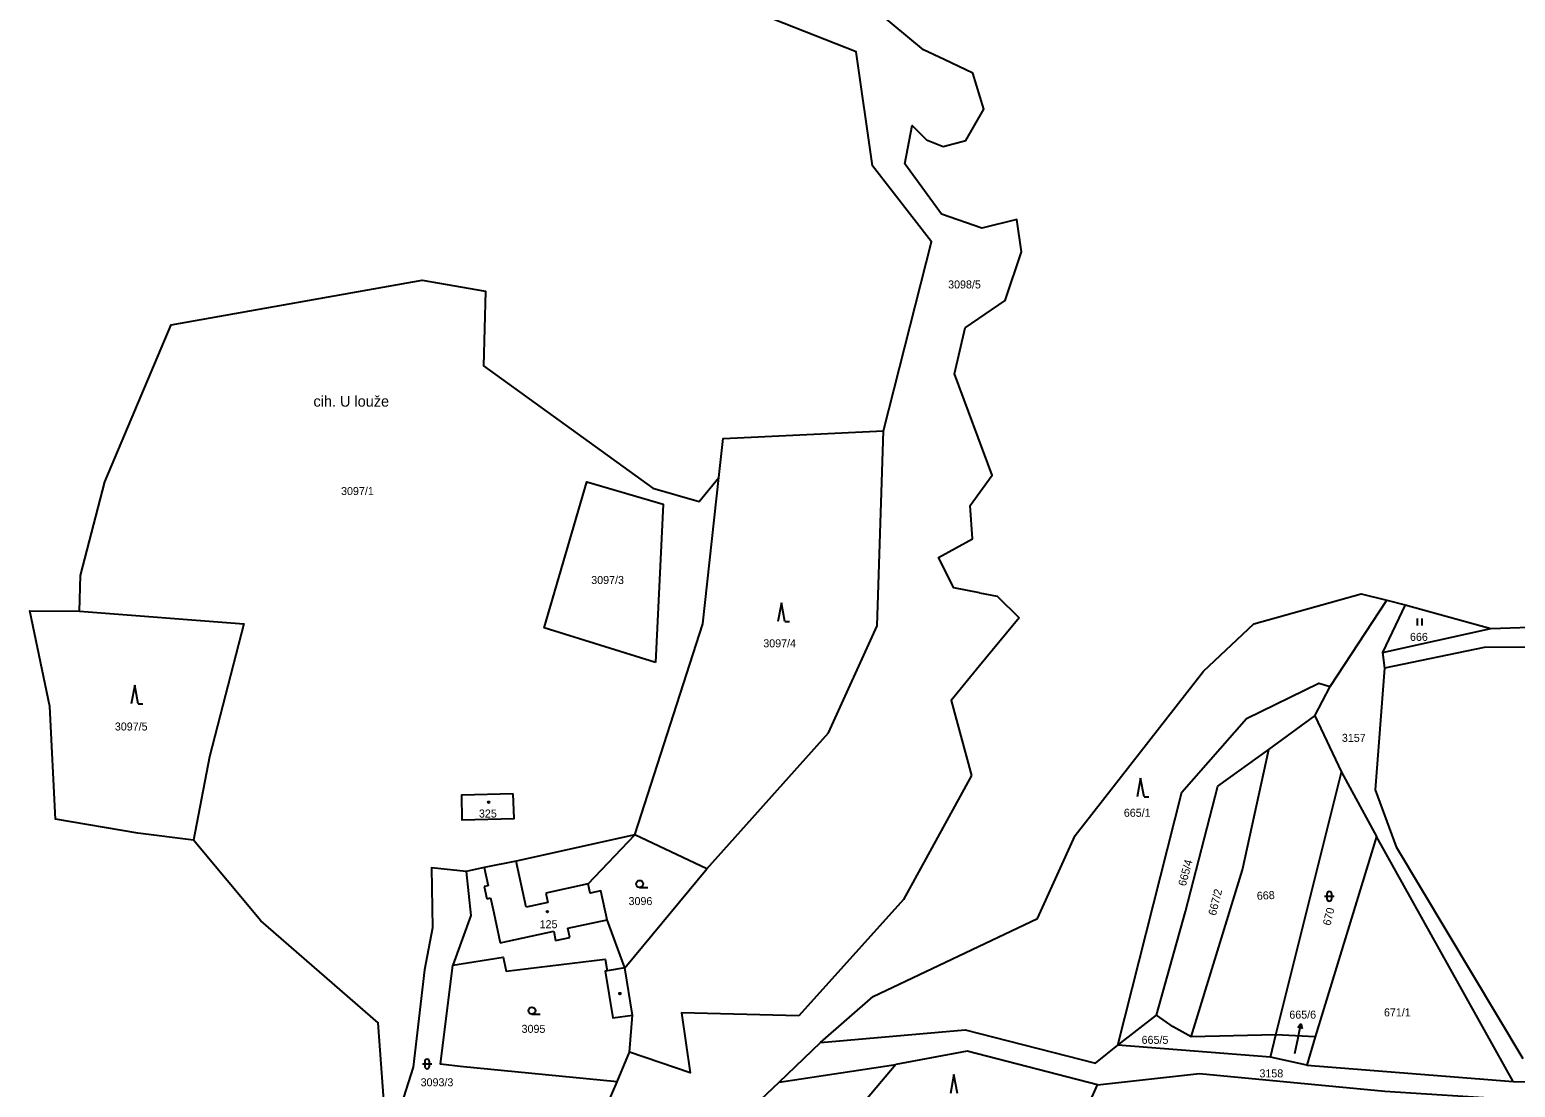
# Model space of a CAD drawing. Extents: x -755528 to -748832, y -1118122 to -1111095.
# Drawn here: x -753590.8 to -753275.1, y -1113366.7 to -1113142 of the extents above; entities that cross this region are included whole.
import ezdxf

# ---------------------------------------------------------------- set-up
doc = ezdxf.new("R2010")
doc.units = 0
for name, color, linetype in [('DZ_DO_ostatní', 7, 'Continuous'), ('DZ_DO_PUPFL', 7, 'Continuous'), ('DZ_NAD_PUPFL', 7, 'Continuous'), ('DZ_NAD_ZPF', 7, 'Continuous'), ('legenda barvy', 7, 'Continuous'), ('legenda_text', 7, 'Continuous'), ('TZ_UMVŽST', 7, 'Continuous')]:
    doc.layers.add(name, color=color, linetype=linetype)

msp = doc.modelspace()

# ---------------------------------------------------------------- linework, layer by layer
at = {"layer": 'DZ_DO_ostatní'}
for p, q in [((-753485.28, -1113328.44), (-753487.4, -1113318.68)), ((-753494.24, -1113320.04), (-753493.41, -1113323.91)), ((-753493.41, -1113323.91), (-753494.2, -1113324.07)), ((-753494.2, -1113324.07), (-753493.64, -1113326.67)), ((-753472.11, -1113323.54), (-753481.11, -1113325.46)), ((-753493.64, -1113326.67), (-753492.86, -1113326.5)), ((-753492.86, -1113326.5), (-753492.19, -1113329.64)), ((-753480.67, -1113327.44), (-753485.28, -1113328.44)), ((-753481.11, -1113325.46), (-753480.67, -1113327.44)), ((-753492.19, -1113329.64), (-753490.82, -1113336.04)), ((-753476.48, -1113332.96), (-753468.06, -1113331.15)), ((-753490.82, -1113336.04), (-753479.46, -1113333.6)), ((-753479.46, -1113333.6), (-753479.04, -1113335.53)), ((-753476.06, -1113334.89), (-753476.48, -1113332.96)), ((-753479.04, -1113335.53), (-753476.06, -1113334.89)), ((-753464.35, -1113341.39), (-753468.1, -1113342.01))]:
    msp.add_line(p, q, dxfattribs=at)
at = {"layer": 'DZ_NAD_PUPFL'}
for p, q in [((-753400.84, -1113146.33), (-753421.97, -1113128.74)), ((-753396.45, -1113148.39), (-753400.84, -1113146.33)), ((-753302.42, -1113263.25), (-753298.54, -1113264.25)), ((-753298.54, -1113264.25), (-753280.3, -1113269.23)), ((-753280.3, -1113269.23), (-753200.9, -1113266.87)), ((-753368.68, -1113313.21), (-753341.36, -1113278.31)), ((-753376.67, -1113330.87), (-753368.68, -1113313.21)), ((-753411.57, -1113347.48), (-753376.67, -1113330.87)), ((-753422.75, -1113357.21), (-753411.57, -1113347.48)), ((-753465.97, -1113365.59), (-753463.34, -1113359.27)), ((-753431.57, -1113365.62), (-753422.75, -1113357.21)), ((-753467.79, -1113369.84), (-753465.97, -1113365.59)), ((-753436.84, -1113370.67), (-753431.57, -1113365.62))]:
    msp.add_line(p, q, dxfattribs=at)
for points in [[(-753388.94, -1113261.67), (-753394.45, -1113260.63), (-753397.71, -1113254.18), (-753390.46, -1113250.18), (-753390.96, -1113243.14), (-753386.31, -1113236.65), (-753394.27, -1113215.13), (-753392.03, -1113205.39), (-753383.51, -1113199.54), (-753380.05, -1113189.19), (-753381.07, -1113182.32), (-753388.49, -1113184.18), (-753397.07, -1113181.24), (-753404.84, -1113170.52), (-753403.28, -1113162.39), (-753400.27, -1113165.43), (-753396.69, -1113166.82), (-753391.91, -1113165.6), (-753388.05, -1113158.93), (-753390.39, -1113151.24), (-753396.45, -1113148.39)], [(-753388.94, -1113261.67), (-753385.19, -1113262.37), (-753380.54, -1113267), (-753388.95, -1113277.21)], [(-753341.36, -1113278.31), (-753330.71, -1113268.26), (-753307.88, -1113261.86), (-753302.42, -1113263.25)], [(-753388.95, -1113277.21), (-753394.99, -1113284.54), (-753390.69, -1113300.5)], [(-753390.69, -1113300.5), (-753405.11, -1113326.82), (-753427.37, -1113351.56)], [(-753427.37, -1113351.56), (-753452.29, -1113350.95), (-753450.46, -1113363.67), (-753463.34, -1113359.27)]]:
    msp.add_lwpolyline(points, dxfattribs=at)
at = {"layer": 'DZ_NAD_ZPF'}
for p, q in [((-753314.47, -1113281.6), (-753302.42, -1113263.25)), ((-753298.54, -1113264.25), (-753303.35, -1113274.33)), ((-753303.35, -1113274.33), (-753280.3, -1113269.23)), ((-753303.35, -1113274.33), (-753302.88, -1113277.71)), ((-753317.74, -1113287.82), (-753314.47, -1113281.6)), ((-753327.52, -1113294.94), (-753317.74, -1113287.82)), ((-753317.74, -1113287.82), (-753312.05, -1113299.81)), ((-753325.99, -1113355.6), (-753312.05, -1113299.81)), ((-753312.05, -1113299.81), (-753304.61, -1113313.47)), ((-753446.94, -1113320.34), (-753462.2, -1113313.1)), ((-753304.61, -1113313.47), (-753317.62, -1113356.05)), ((-753275.56, -1113365.48), (-753304.61, -1113313.47)), ((-753464.35, -1113341.39), (-753446.94, -1113320.34)), ((-753462.71, -1113351.38), (-753464.35, -1113341.39)), ((-753463.34, -1113359.27), (-753462.71, -1113351.38)), ((-753359.6, -1113357.76), (-753351.38, -1113351.42)), ((-753325.99, -1113355.6), (-753344.02, -1113356.02)), ((-753327.17, -1113360.31), (-753325.99, -1113355.6)), ((-753317.62, -1113356.05), (-753325.99, -1113355.6)), ((-753317.62, -1113356.05), (-753319.45, -1113362.05)), ((-753327.17, -1113360.31), (-753359.6, -1113357.76)), ((-753431.57, -1113365.62), (-753406.72, -1113361.91)), ((-753319.45, -1113362.05), (-753327.17, -1113360.31)), ((-753319.45, -1113362.05), (-753275.56, -1113365.48)), ((-753275.56, -1113365.48), (-753270.58, -1113365.56))]:
    msp.add_line(p, q, dxfattribs=at)
for points in [[(-753409.38, -1113227.23), (-753399.14, -1113187.13), (-753411.72, -1113170.92), (-753415.16, -1113146.75), (-753437.11, -1113138.11), (-753439.22, -1113123.97), (-753455.54, -1113119.41), (-753469.06, -1113100.91), (-753482.8, -1113078.07), (-753518.69, -1113046.2)], [(-753580.2, -1113265.59), (-753580, -1113258.01), (-753574.83, -1113238.12), (-753560.77, -1113204.72), (-753507.43, -1113195.21), (-753493.95, -1113197.61), (-753494.34, -1113213.43), (-753458.39, -1113239.45), (-753448.54, -1113242.28), (-753444.37, -1113237.2)], [(-753446.94, -1113320.34), (-753421.04, -1113291.39), (-753410.75, -1113268.68), (-753409.38, -1113227.23)], [(-753444.37, -1113237.2), (-753443.46, -1113228.92), (-753409.38, -1113227.23)], [(-753457.8, -1113276.48), (-753481.46, -1113269.11), (-753472.4, -1113238.06), (-753456.18, -1113242.84), (-753457.8, -1113276.48)], [(-753462.2, -1113313.1), (-753447.78, -1113268.28), (-753444.37, -1113237.2)], [(-753556.03, -1113314.21), (-753567.8, -1113312.71), (-753585.35, -1113309.75), (-753586.53, -1113285.83), (-753590.8, -1113265.52), (-753580.2, -1113265.59)], [(-753580.2, -1113265.59), (-753545.29, -1113268.24), (-753552.58, -1113296.52), (-753556.03, -1113314.21)], [(-753201.29, -1113269.39), (-753203.47, -1113269.54), (-753244.55, -1113273.19), (-753281.75, -1113273.29), (-753302.88, -1113277.71)], [(-753302.88, -1113277.71), (-753304.9, -1113303.55), (-753300.43, -1113315.62), (-753273.54, -1113360.6)], [(-753359.6, -1113357.76), (-753346, -1113304.05), (-753332.23, -1113288.37), (-753316.86, -1113280.9), (-753314.47, -1113281.6)], [(-753351.38, -1113351.42), (-753345.17, -1113329.36), (-753338.3, -1113302.78), (-753327.52, -1113294.94)], [(-753344.02, -1113356.02), (-753333.11, -1113320.51), (-753327.52, -1113294.94)], [(-753488.09, -1113304.39), (-753499.08, -1113304.64), (-753498.97, -1113309.88), (-753487.89, -1113309.65), (-753488.09, -1113304.39)], [(-753515.14, -1113375.26), (-753516.75, -1113353.04), (-753541.71, -1113331.35), (-753556.03, -1113314.21)], [(-753462.2, -1113313.1), (-753487.4, -1113318.68), (-753494.24, -1113320.04), (-753498.05, -1113320.86)], [(-753464.35, -1113341.39), (-753468.06, -1113331.15), (-753469.44, -1113325.01), (-753471.69, -1113325.49), (-753472.11, -1113323.54), (-753462.2, -1113313.1)], [(-753498.05, -1113320.86), (-753505.43, -1113320.08), (-753505.24, -1113332.85), (-753506.88, -1113341.79), (-753509.32, -1113362.45), (-753511.87, -1113370.49), (-753515.14, -1113375.26)], [(-753498.05, -1113320.86), (-753497.08, -1113330.22), (-753500.88, -1113340.77)], [(-753465.97, -1113365.59), (-753499.32, -1113362.34), (-753503.52, -1113361.83), (-753500.88, -1113340.77)], [(-753500.88, -1113340.77), (-753490.17, -1113339.07), (-753489.53, -1113342.05), (-753468.51, -1113339.54), (-753468.1, -1113342.01), (-753468.5, -1113342.07), (-753466.9, -1113352), (-753462.71, -1113351.38)], [(-753344.02, -1113356.02), (-753347.83, -1113353.88), (-753351.38, -1113351.42)], [(-753422.75, -1113357.21), (-753392.05, -1113354.55), (-753364.33, -1113361.63), (-753359.6, -1113357.76)], [(-753363.92, -1113366.23), (-753391.58, -1113359.07), (-753406.72, -1113361.91)], [(-753406.72, -1113361.91), (-753416.23, -1113373.14), (-753420.65, -1113389.28)], [(-753363.92, -1113366.23), (-753342.23, -1113363.82), (-753302.87, -1113367.57), (-753276.25, -1113369.24)], [(-753396.29, -1113381.11), (-753390.98, -1113377.03), (-753368.04, -1113375.41), (-753363.92, -1113366.23)]]:
    msp.add_lwpolyline(points, dxfattribs=at)
at = {"layer": 'legenda barvy'}
for p, q in [((-753320.666, -1113353.265), (-753321.364, -1113354.14)), ((-753321.29, -1113356.2), (-753320.666, -1113353.265)), ((-753320.666, -1113353.265), (-753320.384, -1113354.348)), ((-753322, -1113359.53), (-753321.29, -1113356.2))]:
    msp.add_line(p, q, dxfattribs=at)
at = {"layer": 'legenda_text'}
for centre in [(-753493.2568, -1113306.1592), (-753480.8068, -1113329.4392), (-753465.3968, -1113346.8192)]:
    msp.add_circle(centre, 0.175, dxfattribs=at)
at = {"layer": 'TZ_UMVŽST'}
for p, q in [((-753431.06, -1113263.78), (-753431.81, -1113267.78)), ((-753430.31, -1113267.78), (-753431.06, -1113263.78)), ((-753430.31, -1113267.78), (-753429.314, -1113267.78)), ((-753295.901, -1113268.64), (-753295.901, -1113267.14)), ((-753294.9, -1113268.64), (-753294.9, -1113267.14)), ((-753568.49, -1113281.28), (-753569.24, -1113285.28)), ((-753567.74, -1113285.28), (-753568.49, -1113281.28)), ((-753567.74, -1113285.28), (-753566.744, -1113285.28)), ((-753354.74, -1113301.04), (-753355.49, -1113305.04)), ((-753353.99, -1113305.04), (-753354.74, -1113301.04)), ((-753353.99, -1113305.04), (-753352.994, -1113305.04)), ((-753461.203, -1113324.27), (-753459.453, -1113324.27)), ((-753315.641, -1113326.161), (-753313.639, -1113326.161)), ((-753315.141, -1113325.661), (-753315.141, -1113326.662)), ((-753314.139, -1113326.662), (-753314.139, -1113325.661)), ((-753484.083, -1113351.21), (-753482.333, -1113351.21)), ((-753507.351, -1113361.781), (-753505.349, -1113361.781)), ((-753506.851, -1113361.281), (-753506.851, -1113362.282)), ((-753505.849, -1113362.282), (-753505.849, -1113361.281)), ((-753394.4, -1113364.04), (-753395.15, -1113368.04)), ((-753393.65, -1113368.04), (-753394.4, -1113364.04))]:
    msp.add_line(p, q, dxfattribs=at)
for centre in [(-753461.2029, -1113323.5198), (-753484.0829, -1113350.4598)]:
    msp.add_circle(centre, 0.75, dxfattribs=at)
for centre, start, end in [((-753314.64, -1113325.6609), 0, 180), ((-753314.64, -1113326.6609), 180, 359.987886), ((-753506.35, -1113361.2809), 0, 180), ((-753506.35, -1113362.2809), 180, 359.987886)]:
    msp.add_arc(centre, 0.5, start, end, dxfattribs=at)

# ---------------------------------------------------------------- texts
at = {"layer": 'DZ_DO_PUPFL'}
for s, p in [('3098/5', (-753395.64, -1113197)), ('3097/1', (-753524.64, -1113240.9)), ('3097/3', (-753471.48, -1113259.8)), ('666', (-753297.5, -1113271.89)), ('3097/4', (-753434.92, -1113273.25)), ('3097/5', (-753572.71, -1113290.93)), ('3157', (-753311.97, -1113293.34)), ('325', (-753495.34, -1113309.42)), ('665/1', (-753358.31, -1113309.26)), ('3096', (-753463.55, -1113328.02)), ('125', (-753482.45, -1113332.94)), ('671/1', (-753303.03, -1113351.67)), ('665/6', (-753323.14, -1113352.15)), ('3095', (-753486.28, -1113355.17)), ('665/5', (-753354.528, -1113357.51)), ('3093/3', (-753507.73, -1113366.52)), ('3158', (-753329.49, -1113364.63))]:
    msp.add_text(s, height=1.7, dxfattribs=at).set_placement(p)
for s, rotation, p in [('665/4', 75, (-753345.158, -1113324.119)), ('667/2', 76, (-753338.755, -1113330.365)), ('668', 3, (-753330.005, -1113326.918)), ('670', 76, (-753314.425, -1113332.495))]:
    msp.add_text(s, height=1.7, rotation=rotation, dxfattribs=at).set_placement(p)
at = {"layer": 'legenda barvy'}
msp.add_text('cih. U louže', height=2.299998, dxfattribs=at).set_placement((-753530.501, -1113222.12))

doc.saveas('drawing.dxf')
